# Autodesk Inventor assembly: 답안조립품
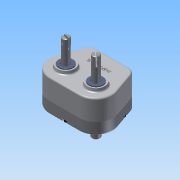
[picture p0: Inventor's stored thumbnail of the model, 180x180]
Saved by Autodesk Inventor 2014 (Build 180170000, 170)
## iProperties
Created: 2014-12
Part Number: 답안조립품
Document SubType Name: Assembly
Designer: user
Author: user
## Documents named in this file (13)
- C:\Users\user\Desktop\441208V1025\답안조립품.iam
- C:\Users\user\Desktop\441208V1025\본체.ipt
- C:\Users\user\Desktop\441208V1025\커버.ipt
- C:\Users\user\Desktop\441208V1025\오일시일-D-17.ipt
- C:\Users\user\Desktop\441208V1025\베어링- 6202.ipt
- C:\Users\user\Desktop\441208V1025\서브축.ipt
- C:\Users\user\Desktop\441208V1025\베어링- 6203.ipt
- C:\Users\user\Desktop\441208V1025\키5x5.ipt
- C:\Users\user\Desktop\441208V1025\서브기어.ipt
- C:\Users\user\Desktop\441208V1025\멈춤링.ipt
- C:\Users\user\Desktop\441208V1025\메인축.ipt
- C:\Users\user\Desktop\441208V1025\메인기어.ipt
- C:\Users\user\Desktop\441208V1025\M 5 x 35.ipt
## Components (15 placed, 5 different names)
1. KS B 2804 D D - 17 30 8:1
2. KS B 2804 D D - 17 30 8:2
3. KS B 2804 D D - 17 30 8:3
4. KS B 2023 6202 - 15 x 35 x 11:1
5. KS B 2023 6202 - 15 x 35 x 11:2
6. KS B 2023 6203 - 17 x 40 x 12:1
7. KS B 2023 6203 - 17 x 40 x 12:2
8. KS B 1336 17 x 1:1
9. KS B 1336 17 x 1:2
10. KS B 2023 6203 - 17 x 40 x 12:3
11. KS B 1336 17 x 1:3
12. KS B 2023 6203 - 17 x 40 x 12:4
13. KS B 1003 - 미터 M 5 x 35:1 — 각도:9
14. KS B 1003 - 미터 M 5 x 35:2 — 각도:8
15. KS B 1003 - 미터 M 5 x 35:3 — 각도:7
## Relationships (3: Angle 3)
- 각도:7 [Angle]: KS B 1003 - 미터 M 5 x 35:3
- 각도:8 [Angle]: KS B 1003 - 미터 M 5 x 35:2
- 각도:9 [Angle]: KS B 1003 - 미터 M 5 x 35:1
